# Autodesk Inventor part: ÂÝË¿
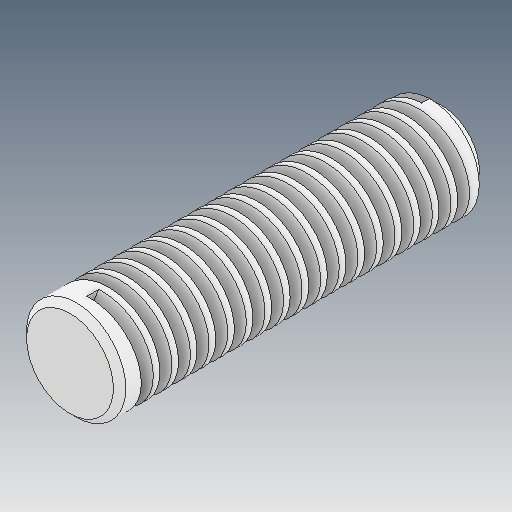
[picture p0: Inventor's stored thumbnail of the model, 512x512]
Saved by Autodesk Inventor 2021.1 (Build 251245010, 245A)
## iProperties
Created: 2021-05
Part Number: ÂÝË¿
Material: Ogólny
Document SubType Name: Modeling
Designer: user
Density: 1 g/cm^3
Appearance: Domyślna
Author: user
Revision Number: ÈÎºÎ
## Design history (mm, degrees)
feature "ÊäÈë1"
node "Bryła1"
